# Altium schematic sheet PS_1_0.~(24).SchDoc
size A4
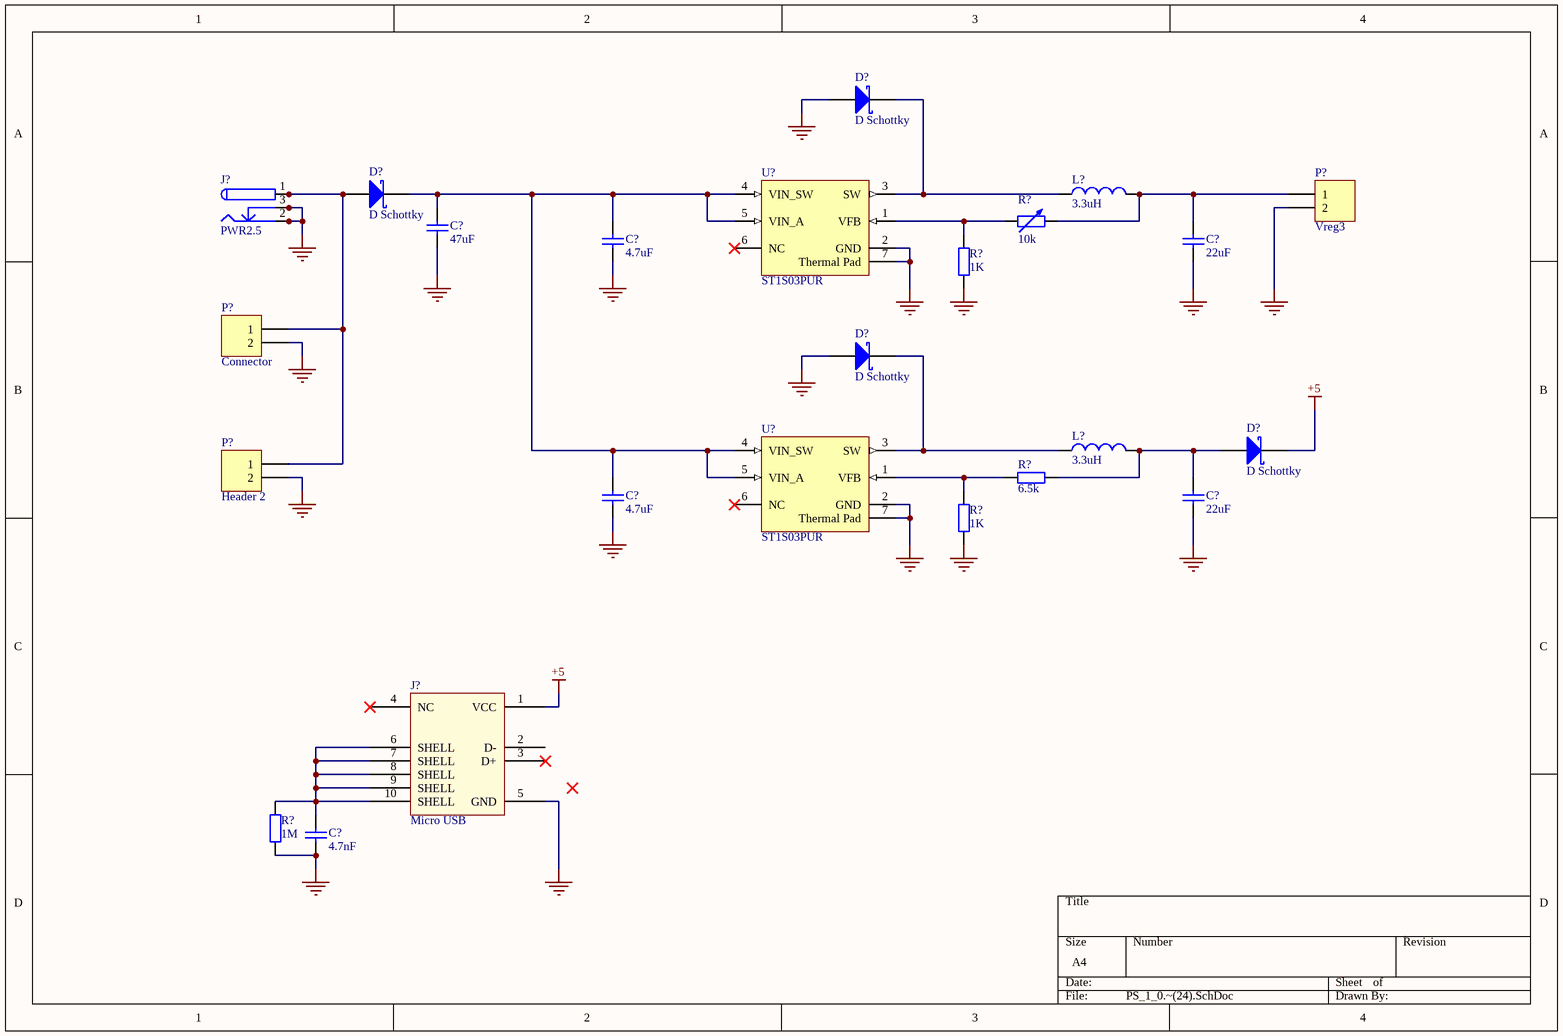
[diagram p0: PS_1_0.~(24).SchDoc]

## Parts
(Parts that share a designator on the sheet are numbered #1, #2 ... from top to bottom, then left to right.)
C?#1  47uF  [C0805]
C?#2  4.7uF  [C0805]
C?#3  22uF  [C0805]
C?#4  4.7uF  [C0805]
C?#5  22uF  [C0805]
C?#6  4.7nF  [0603]
D?#1  D Schottky  [SMB]
D?#2  D Schottky  [SMB]
D?#3  D Schottky  [SMB]
D?#4  D Schottky  [SMB]
J?#1  PWR2.5  [KLD-0202]
J?#2  Micro USB
L?#1  3.3uH  [0402-A]
L?#2  3.3uH  [0402-A]
P?#1  Vreg3  [HDR1X2]
P?#2  Connector  [L_ZAC]
P?#3  Header 2  [HDR1X2]
R?#1  10k  [AXIAL-0.6]
R?#2  1K  [0603]
R?#3  6.5k  [0603]
R?#4  1K  [0603]
R?#5  1M  [0603]
U?#1  ST1S03PUR  [DFN6D_M]
U?#2  ST1S03PUR  [DFN6D_M]

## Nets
+5: D?#4.2(K) J?#2.1(VCC)
GND: C?#1.2 C?#2.2 C?#3.2 C?#4.2 C?#5.2 C?#6.2 D?#1.1(A) D?#3.1(A) J?#1.2 J?#1.2A J?#1.2B J?#1.3 J?#1.3A J?#1.3B J?#2.5(GND) P?#1.2 P?#2.2 P?#3.2 R?#2.1 R?#4.1 R?#5.1 U?#1.2(GND) U?#1.7(Thermal_Pad) U?#2.2(GND) U?#2.7(Thermal_Pad)
NetC?#1_1: C?#1.1 C?#2.1 C?#4.1 D?#2.2(K) U?#1.4(VIN_SW) U?#1.5(VIN_A) U?#2.4(VIN_SW) U?#2.5(VIN_A)
NetC?#3_1: C?#3.1 L?#1.2 P?#1.1 R?#1.2
NetC?#5_1: C?#5.1 D?#4.1(A) L?#2.2 R?#3.1
NetC?#6_1: C?#6.1 J?#2.6(SHELL) J?#2.7(SHELL) J?#2.8(SHELL) J?#2.9(SHELL) J?#2.10(SHELL) R?#5.2
NetD?#1_2: D?#1.2(K) L?#1.1 U?#1.3(SW)
NetD?#2_1: D?#2.1(A) J?#1.1 J?#1.1A J?#1.1B P?#2.1 P?#3.1
NetD?#3_2: D?#3.2(K) L?#2.1 U?#2.3(SW)
NetR?#1_1: R?#1.1 R?#2.2 U?#1.1(VFB)
NetR?#3_2: R?#3.2 R?#4.2 U?#2.1(VFB)

Not connected (* = marked no-connect by the designer): J?#2 2(D-) 3(D+)* 4(NC)*; U?#1 6(NC)*; U?#2 6(NC)*

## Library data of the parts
C?#1-C?#6 = Cap Semi: Capacitor (Semiconductor SIM Model)
D?#1-D?#4 = D Schottky: Schottky Diode
J?#1 = PWR2.5: Low Voltage Power Supply Connector
J?#2 = Micro USB: type B
L?#1 L?#2 = Inductor: Code_IEC: 1005
P?#1-P?#3 = Header 2: Header, 2-Pin
R?#1 = Res Adj2: Variable Resistor; Set Position: 0.5
R?#2-R?#5 = Res2: Resistor
U?#1 U?#2 = ST1S03PUR: 1.5 A, 1.5 MHz adjustable, step-down switching regulator, DFN6D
